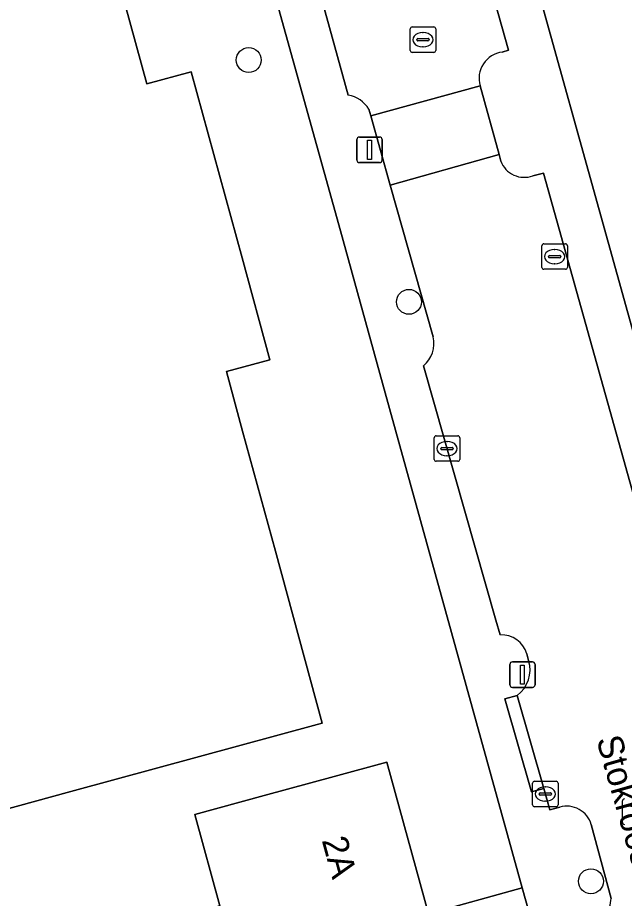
# Model space of a CAD drawing. Extents: x 162250 to 162661, y 380743 to 381606.
# Drawn here: x 162422.34 to 162446.15, y 381294 to 381328.57 of the extents above; entities that cross this region are included whole.
import ezdxf

# ---------------------------------------------------------------- set-up
doc = ezdxf.new("R2010")
doc.units = 0
for name, color, linetype in [('IMGEO_Boom', 7, 'Continuous'), ('IMGEO_Erf', 7, 'Continuous'), ('IMGEO_Kolk', 7, 'Continuous'), ('IMGEO_Lichtmast', 7, 'Continuous'), ('IMGEO_Openbare_ruimte_label', 7, 'Continuous'), ('IMGEO_Pand', 7, 'Continuous'), ('IMGEO_Pand_nummerreeks', 7, 'Continuous'), ('IMGEO_Rijbaan_lokaal_open', 7, 'Continuous'), ('IMGEO_Rioolput', 7, 'Continuous'), ('IMGEO_Voetpad_open', 7, 'Continuous')]:
    doc.layers.add(name, color=color, linetype=linetype)

msp = doc.modelspace()

# ---------------------------------------------------------------- linework, layer by layer
at = {"layer": 'IMGEO_Boom'}
for centre in [(162431.41, 381326.905), (162437.693, 381317.412), (162444.835, 381294.671)]:
    msp.add_circle(centre, 0.489, dxfattribs=at)
at = {"layer": 'IMGEO_Erf'}
for points in [[(162419.551, 381288.338), (162425.667, 381290.132), (162429.605, 381291.207), (162429.017, 381293.362), (162430.274, 381293.705), (162429.295, 381297.292), (162432.01, 381298.033), (162434.759, 381298.784), (162436.833, 381299.35), (162438.459, 381293.393), (162442.142, 381294.412), (162436.765, 381313.847), (162435.015, 381320.204), (162426.714, 381350.004), (162406.556, 381344.473)], [(162437.221, 381349.572), (162450.776, 381300.808), (162465.094, 381250)], [(162417.882, 381341.494), (162423.284, 381340.745), (162425.621, 381332.181), (162426.342, 381331.991), (162426.955, 381329.744), (162426.568, 381329.066), (162427.413, 381325.969), (162429.151, 381326.443), (162431.146, 381319.134), (162432.236, 381315.138), (162430.533, 381314.674), (162431.171, 381312.334), (162432.454, 381307.629), (162434.297, 381300.878), (162434.095, 381300.823), (162429.474, 381299.562), (162424.435, 381298.186), (162419.606, 381296.868)]]:
    msp.add_lwpolyline(points, dxfattribs=at)
at = {"layer": 'IMGEO_Kolk'}
for p, q in [((162442.911, 381318.763), (162442.911, 381319.615)), ((162442.986, 381319.689), (162443.838, 381319.689)), ((162443.399, 381319.469), (162443.424, 381319.469)), ((162443.912, 381319.615), (162443.912, 381318.763)), ((162443.17, 381319.183), (162443.17, 381319.195)), ((162443.608, 381319.146), (162443.21, 381319.146)), ((162443.213, 381319.232), (162443.611, 381319.232)), ((162443.654, 381319.195), (162443.654, 381319.183)), ((162443.422, 381318.909), (162443.397, 381318.909)), ((162443.838, 381318.689), (162442.986, 381318.689)), ((162438.764, 381312.153), (162439.616, 381312.153)), ((162438.689, 381311.227), (162438.689, 381312.079)), ((162439.177, 381311.933), (162439.202, 381311.933)), ((162439.69, 381312.079), (162439.69, 381311.227)), ((162438.948, 381311.647), (162438.948, 381311.659)), ((162439.386, 381311.61), (162438.988, 381311.61)), ((162438.991, 381311.696), (162439.389, 381311.696)), ((162439.432, 381311.659), (162439.432, 381311.647)), ((162439.616, 381311.153), (162438.764, 381311.153)), ((162439.2, 381311.373), (162439.175, 381311.373)), ((162442.545, 381297.67), (162442.545, 381298.522)), ((162442.62, 381298.596), (162443.472, 381298.596)), ((162443.033, 381298.376), (162443.058, 381298.376)), ((162443.546, 381298.522), (162443.546, 381297.67)), ((162442.804, 381298.09), (162442.804, 381298.102)), ((162443.242, 381298.053), (162442.844, 381298.053)), ((162442.847, 381298.139), (162443.245, 381298.139)), ((162443.288, 381298.102), (162443.288, 381298.09)), ((162443.056, 381297.816), (162443.031, 381297.816)), ((162443.472, 381297.596), (162442.62, 381297.596))]:
    msp.add_line(p, q, dxfattribs=at)
for points in [[(162442.911, 381318.763), (162442.911, 381319.615)], [(162442.986, 381319.689), (162443.838, 381319.689)], [(162443.912, 381319.615), (162443.912, 381318.763)], [(162443.838, 381318.689), (162442.986, 381318.689)], [(162438.764, 381312.153), (162439.616, 381312.153)], [(162438.689, 381311.227), (162438.689, 381312.079)], [(162439.69, 381312.079), (162439.69, 381311.227)], [(162439.616, 381311.153), (162438.764, 381311.153)], [(162442.545, 381297.67), (162442.545, 381298.522)], [(162442.62, 381298.596), (162443.472, 381298.596)], [(162443.546, 381298.522), (162443.546, 381297.67)], [(162443.472, 381297.596), (162442.62, 381297.596)]]:
    msp.add_lwpolyline(points, dxfattribs=at)
for centre, radius, start, end in [((162442.988, 381319.613), 0.0765, 91.552, 178.448), ((162442.988, 381319.613), 0.0765, 91.552, 178.448), ((162443.836, 381319.613), 0.0765, 1.552, 88.448), ((162443.836, 381319.613), 0.0765, 1.552, 88.448), ((162443.21, 381319.192), 0.0403, 85.8775, 175.7526), ((162443.207, 381319.182), 0.0366, 178.938, 274.7102), ((162443.611, 381319.189), 0.043, 264.8664, 352.4533), ((162443.615, 381319.194), 0.0386, 1.7309, 96.639), ((162442.988, 381318.765), 0.0765, 181.552, 268.448), ((162442.988, 381318.765), 0.0765, 181.552, 268.448), ((162443.836, 381318.765), 0.0765, 271.552, 358.448), ((162443.836, 381318.765), 0.0765, 271.552, 358.448), ((162438.766, 381312.077), 0.0765, 91.552, 178.448), ((162438.766, 381312.077), 0.0765, 91.552, 178.448), ((162439.614, 381312.077), 0.0765, 1.552, 88.448), ((162439.614, 381312.077), 0.0765, 1.552, 88.448), ((162438.988, 381311.656), 0.0403, 85.8775, 175.7526), ((162438.985, 381311.646), 0.0366, 178.938, 274.7102), ((162439.389, 381311.653), 0.043, 264.8664, 352.4533), ((162439.393, 381311.658), 0.0386, 1.7309, 96.639), ((162438.766, 381311.229), 0.0765, 181.552, 268.448), ((162438.766, 381311.229), 0.0765, 181.552, 268.448), ((162439.614, 381311.229), 0.0765, 271.552, 358.448), ((162439.614, 381311.229), 0.0765, 271.552, 358.448), ((162442.622, 381298.52), 0.0765, 91.552, 178.448), ((162442.622, 381298.52), 0.0765, 91.552, 178.448), ((162443.47, 381298.52), 0.0765, 1.552, 88.448), ((162443.47, 381298.52), 0.0765, 1.552, 88.448), ((162442.844, 381298.099), 0.0403, 85.8775, 175.7526), ((162442.841, 381298.089), 0.0366, 178.938, 274.7102), ((162443.245, 381298.096), 0.043, 264.8664, 352.4533), ((162443.249, 381298.101), 0.0386, 1.7309, 96.639), ((162442.622, 381297.672), 0.0765, 181.552, 268.448), ((162442.622, 381297.672), 0.0765, 181.552, 268.448), ((162443.47, 381297.672), 0.0765, 271.552, 358.448), ((162443.47, 381297.672), 0.0765, 271.552, 358.448)]:
    msp.add_arc(centre, radius, start, end, dxfattribs=at)
for centre, major_axis, ratio, start_param, end_param in [((162443.398, 381319.189), (-0.387, 0.002), 0.722429, 4.712389, 7.853982), ((162443.423, 381319.189), (-0.39, 0.002), 0.717154, 1.570796, 4.712389), ((162439.176, 381311.653), (-0.387, 0.002), 0.722429, 4.712389, 7.853982), ((162439.201, 381311.653), (-0.39, 0.002), 0.717154, 1.570796, 4.712389), ((162443.032, 381298.096), (-0.387, 0.002), 0.722429, 4.712389, 7.853982), ((162443.057, 381298.096), (-0.39, 0.002), 0.717154, 1.570796, 4.712389)]:
    msp.add_ellipse(centre, major_axis=major_axis, ratio=ratio, start_param=start_param, end_param=end_param, dxfattribs=at)
at = {"layer": 'IMGEO_Lichtmast'}
for p, q in [((162435.654, 381322.98), (162435.654, 381323.78)), ((162435.654, 381323.78), (162435.654, 381322.98)), ((162435.754, 381323.88), (162436.544, 381323.88)), ((162436.544, 381323.88), (162435.754, 381323.88)), ((162436.644, 381323.78), (162436.644, 381322.98)), ((162436.644, 381322.98), (162436.644, 381323.78)), ((162436.544, 381322.88), (162435.754, 381322.88)), ((162435.754, 381322.88), (162436.544, 381322.88)), ((162441.652, 381302.381), (162441.652, 381303.181)), ((162441.652, 381303.181), (162441.652, 381302.381)), ((162441.752, 381303.281), (162442.542, 381303.281)), ((162442.542, 381303.281), (162441.752, 381303.281)), ((162442.642, 381303.181), (162442.642, 381302.381)), ((162442.642, 381302.381), (162442.642, 381303.181)), ((162442.542, 381302.281), (162441.752, 381302.281)), ((162441.752, 381302.281), (162442.542, 381302.281))]:
    msp.add_line(p, q, dxfattribs=at)
for points in [[(162436.074, 381323.755), (162436.224, 381323.755), (162436.224, 381323.005), (162436.074, 381323.005), (162436.074, 381323.755)], [(162442.072, 381303.156), (162442.222, 381303.156), (162442.222, 381302.406), (162442.072, 381302.406), (162442.072, 381303.156)]]:
    msp.add_lwpolyline(points, dxfattribs=at)
for centre, start, end in [((162435.754, 381323.78), 90, 180), ((162435.754, 381323.78), 90, 180), ((162436.544, 381323.78), 0, 90), ((162436.544, 381323.78), 360, 90), ((162435.754, 381322.98), 180, 270), ((162435.754, 381322.98), 180, 270), ((162436.544, 381322.98), 270, 0), ((162436.544, 381322.98), 270, 0), ((162441.752, 381303.181), 90, 180), ((162441.752, 381303.181), 90, 180), ((162442.542, 381303.181), 0, 90), ((162442.542, 381303.181), 360, 90), ((162441.752, 381302.381), 180, 270), ((162441.752, 381302.381), 180, 270), ((162442.542, 381302.381), 270, 0), ((162442.542, 381302.381), 270, 0)]:
    msp.add_arc(centre, 0.1, start, end, dxfattribs=at)
at = {"layer": 'IMGEO_Pand'}
msp.add_lwpolyline([(162419.606, 381296.868), (162424.435, 381298.186), (162429.474, 381299.562), (162434.095, 381300.823), (162434.297, 381300.878), (162432.454, 381307.629), (162431.171, 381312.334), (162430.533, 381314.674), (162432.236, 381315.138), (162431.146, 381319.134), (162429.151, 381326.443), (162427.413, 381325.969), (162426.568, 381329.066), (162426.955, 381329.744), (162426.342, 381331.991), (162425.621, 381332.181), (162423.284, 381340.745), (162417.882, 381341.494)], dxfattribs=at)
msp.add_lwpolyline([(162436.833, 381299.35), (162434.759, 381298.784), (162432.01, 381298.033), (162429.295, 381297.292), (162430.274, 381293.705), (162429.017, 381293.362), (162429.605, 381291.207), (162429.664, 381290.992), (162433.636, 381292.076), (162438.459, 381293.393)], close=True, dxfattribs=at)
at = {"layer": 'IMGEO_Rijbaan_lokaal_open'}
for points in [[(162441.356, 381327.215), (162441.607, 381327.292), (162435.506, 381348.941)], [(162432.149, 381337.011), (162435.313, 381325.53)], [(162436.126, 381324.971), (162436.2, 381324.71), (162440.483, 381325.893)], [(162441.3, 381322.935), (162441.229, 381323.193), (162436.965, 381321.996), (162438.647, 381316.036)], [(162449.845, 381297.908), (162442.974, 381322.468), (162442.553, 381322.362)], [(162438.265, 381314.901), (162441.109, 381304.924), (162441.275, 381304.342)], [(162442.324, 381303.599), (162442.391, 381303.331)], [(162441.936, 381301.966), (162442.984, 381298.313), (162443.227, 381297.467), (162443.612, 381297.578)], [(162444.848, 381296.893), (162445.624, 381293.997)]]:
    msp.add_lwpolyline(points, dxfattribs=at)
msp.add_lwpolyline([(162441.229, 381323.193), (162440.483, 381325.893), (162436.2, 381324.71), (162436.965, 381321.996)], close=True, dxfattribs=at)
for centre, radius, start, end in [((162441.487, 381326.179), 1.044, 97.1978, 195.9236), ((162435.083, 381324.325), 1.226, 31.7688, 79.2082), ((162442.211, 381323.271), 0.971, 200.248, 290.6025), ((162437.517, 381315.785), 1.158, 310.2644, 12.5328), ((162441.311, 381303.281), 1.062, 17.4386, 91.942), ((162441.222, 381302.962), 1.226, 305.6194, 17.5107), ((162443.888, 381296.619), 0.998, 15.9332, 106.0758), ((162444.09, 381294.07), 1.535, 331.0601, 357.2751)]:
    msp.add_arc(centre, radius, start, end, dxfattribs=at)
at = {"layer": 'IMGEO_Rioolput'}
for p, q in [((162437.744, 381327.275), (162437.744, 381328.127)), ((162437.819, 381328.201), (162438.671, 381328.201)), ((162438.745, 381328.127), (162438.745, 381327.275)), ((162438.003, 381327.695), (162438.003, 381327.707)), ((162438.046, 381327.744), (162438.444, 381327.744)), ((162438.232, 381327.981), (162438.257, 381327.981)), ((162438.487, 381327.707), (162438.487, 381327.695)), ((162438.441, 381327.658), (162438.043, 381327.658)), ((162438.255, 381327.421), (162438.23, 381327.421)), ((162438.671, 381327.201), (162437.819, 381327.201)), ((162446.072, 381296.975), (162446.072, 381297.827))]:
    msp.add_line(p, q, dxfattribs=at)
for points in [[(162437.744, 381327.275), (162437.744, 381328.127)], [(162437.819, 381328.201), (162438.671, 381328.201)], [(162438.745, 381328.127), (162438.745, 381327.275)], [(162438.671, 381327.201), (162437.819, 381327.201)], [(162446.072, 381296.975), (162446.072, 381297.827)]]:
    msp.add_lwpolyline(points, dxfattribs=at)
for centre, radius, start, end in [((162437.821, 381328.125), 0.0765, 91.552, 178.448), ((162437.821, 381328.125), 0.0765, 91.552, 178.448), ((162438.669, 381328.125), 0.0765, 1.552, 88.448), ((162438.669, 381328.125), 0.0765, 1.552, 88.448), ((162438.043, 381327.704), 0.0403, 85.8775, 175.7526), ((162438.448, 381327.706), 0.0386, 1.7309, 96.639), ((162438.04, 381327.694), 0.0366, 178.938, 274.7102), ((162438.444, 381327.701), 0.043, 264.8664, 352.4533), ((162437.821, 381327.277), 0.0765, 181.552, 268.448), ((162437.821, 381327.277), 0.0765, 181.552, 268.448), ((162438.669, 381327.277), 0.0765, 271.552, 358.448), ((162438.669, 381327.277), 0.0765, 271.552, 358.448), ((162446.149, 381297.825), 0.0765, 91.552, 178.448), ((162446.149, 381297.825), 0.0765, 91.552, 178.448), ((162446.149, 381296.977), 0.0765, 181.552, 268.448), ((162446.149, 381296.977), 0.0765, 181.552, 268.448)]:
    msp.add_arc(centre, radius, start, end, dxfattribs=at)
for centre, major_axis, ratio, start_param, end_param in [((162438.231, 381327.701), (-0.387, 0.002), 0.722429, 4.712389, 7.853982), ((162438.256, 381327.701), (-0.39, 0.002), 0.717154, 1.570796, 4.712389)]:
    msp.add_ellipse(centre, major_axis=major_axis, ratio=ratio, start_param=start_param, end_param=end_param, dxfattribs=at)
at = {"layer": 'IMGEO_Voetpad_open'}
for points in [[(162430.504, 381348.496), (162429.829, 381350.907), (162426.714, 381350.004), (162435.015, 381320.204), (162436.765, 381313.847), (162442.142, 381294.412), (162442.682, 381292.462), (162454.43, 381250), (162455.092, 381247.608), (162455.758, 381245.2), (162459.272, 381232.499), (162459.819, 381223.005), (162460.124, 381217.537), (162463.07, 381217.625)], [(162469.535, 381226.012), (162469.398, 381234.727), (162466.151, 381246.25), (162465.361, 381249.054), (162465.094, 381250), (162450.776, 381300.808), (162437.221, 381349.572)], [(162435.506, 381348.941), (162441.607, 381327.292), (162441.356, 381327.215)], [(162435.313, 381325.53), (162432.149, 381337.011)], [(162440.483, 381325.893), (162441.229, 381323.193), (162441.3, 381322.935)], [(162438.647, 381316.036), (162436.965, 381321.996), (162436.2, 381324.71), (162436.126, 381324.971)], [(162442.553, 381322.362), (162442.974, 381322.468), (162449.845, 381297.908), (162455.178, 381278.973), (162454.846, 381278.868)], [(162441.275, 381304.342), (162441.109, 381304.924), (162438.265, 381314.901)], [(162442.391, 381303.331), (162442.324, 381303.599)], [(162443.612, 381297.578), (162443.227, 381297.467), (162442.984, 381298.313), (162442.505, 381298.175), (162441.456, 381301.828), (162441.936, 381301.966)], [(162445.624, 381293.997), (162444.848, 381296.893)], [(162419.659, 381286.162), (162431.316, 381289.346), (162434.194, 381290.132), (162439.017, 381291.448), (162442.682, 381292.462), (162442.142, 381294.412), (162438.459, 381293.393), (162433.636, 381292.076), (162429.664, 381290.992), (162429.605, 381291.207), (162425.667, 381290.132), (162419.551, 381288.338)]]:
    msp.add_lwpolyline(points, dxfattribs=at)
msp.add_lwpolyline([(162442.984, 381298.313), (162441.936, 381301.966), (162441.456, 381301.828), (162442.505, 381298.175)], close=True, dxfattribs=at)
for centre, radius, start, end in [((162441.487, 381326.179), 1.044, 97.1978, 195.9236), ((162435.083, 381324.325), 1.226, 31.7688, 79.2082), ((162442.211, 381323.271), 0.971, 200.248, 290.6025), ((162437.517, 381315.785), 1.158, 310.2644, 12.5328), ((162441.311, 381303.281), 1.062, 17.4386, 91.942), ((162441.222, 381302.962), 1.226, 305.6194, 17.5107), ((162443.888, 381296.619), 0.998, 15.9332, 106.0758), ((162444.09, 381294.07), 1.535, 331.0601, 357.2751)]:
    msp.add_arc(centre, radius, start, end, dxfattribs=at)

# ---------------------------------------------------------------- texts
at = {"layer": 'IMGEO_Openbare_ruimte_label'}
msp.add_text('Stokroosstraat', height=1, rotation=285.9533, dxfattribs=at).set_placement((162445.04, 381300.236))
at = {"layer": 'IMGEO_Pand_nummerreeks'}
msp.add_text('2A', height=1, rotation=285.2691, dxfattribs=at).set_placement((162434.27, 381296.283))

doc.saveas('drawing.dxf')
